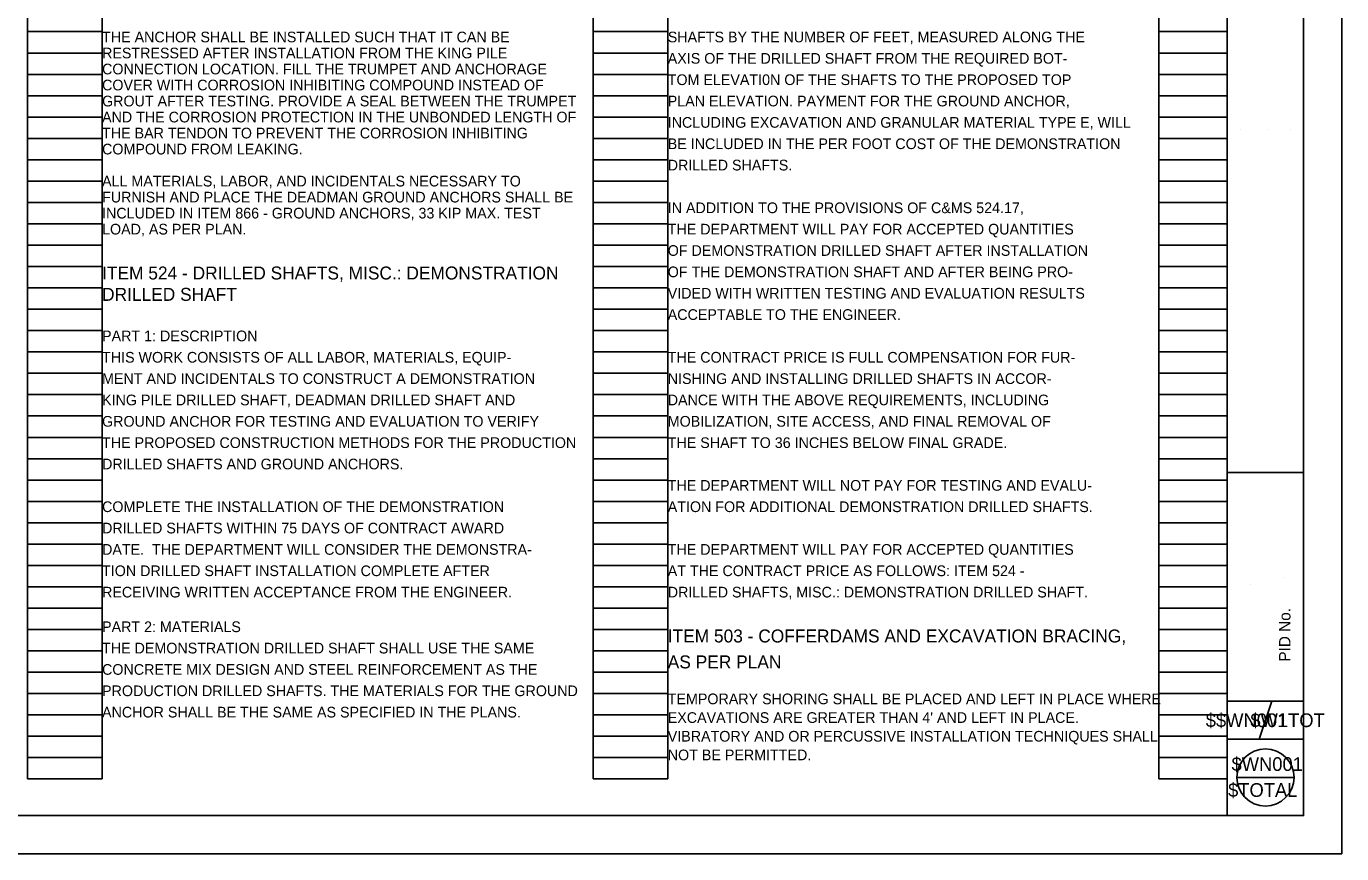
# Model space of a CAD drawing. Extents: x -0.2 to 33.8, y -0.1 to 21.9.
# Drawn here: x 16.52 to 33.78, y -0.13 to 10.72 of the extents above; entities that cross this region are included whole.
import ezdxf

# ---------------------------------------------------------------- set-up
doc = ezdxf.new("R2010")
doc.units = 0
for name, color, linetype in [('SH_Border', 7, 'Continuous'), ('SH_Cut_Line', 7, 'Continuous'), ('SH_Data', 7, 'Continuous'), ('SH_Text', 7, 'Continuous')]:
    doc.layers.add(name, color=color, linetype=linetype)

msp = doc.modelspace()

# ---------------------------------------------------------------- linework, layer by layer
at = {"layer": 'SH_Border'}
for p, q in [((32.275, 0.368), (32.275, 21.368)), ((32.275, 4.868), (33.275, 4.868)), ((32.275, 1.868), (33.275, 1.868)), ((32.692, 1.368), (32.859, 1.868)), ((32.275, 1.368), (33.275, 1.368))]:
    msp.add_line(p, q, dxfattribs=at)
msp.add_lwpolyline([(1.775, 21.368), (33.275, 21.368), (33.275, 0.368), (1.775, 0.368)], close=True, dxfattribs=at)
at = {"layer": 'SH_Cut_Line'}
msp.add_lwpolyline([(-0.225, 21.868), (33.775, 21.868), (33.775, -0.132), (-0.225, -0.132)], close=True, dxfattribs=at)
at = {"layer": 'SH_Data'}
for p, q in [((16.535, 0.848), (16.535, 21.008)), ((17.515, 0.848), (17.515, 21.008)), ((23.955, 0.848), (23.955, 21.008)), ((24.935, 0.848), (24.935, 21.008)), ((31.375, 0.848), (31.375, 21.008)), ((32.275, 0.848), (32.275, 21.008)), ((16.535, 10.648), (17.515, 10.648)), ((23.955, 10.648), (24.935, 10.648)), ((31.375, 10.648), (32.275, 10.648)), ((16.535, 10.368), (17.515, 10.368)), ((23.955, 10.368), (24.935, 10.368)), ((31.375, 10.368), (32.275, 10.368)), ((16.535, 10.088), (17.515, 10.088)), ((23.955, 10.088), (24.935, 10.088)), ((31.375, 10.088), (32.275, 10.088)), ((16.535, 9.808), (17.515, 9.808)), ((23.955, 9.808), (24.935, 9.808)), ((31.375, 9.808), (32.275, 9.808)), ((16.535, 9.528), (17.515, 9.528)), ((23.955, 9.528), (24.935, 9.528)), ((31.375, 9.528), (32.275, 9.528)), ((32.442, 9.368), (32.442, 9.368)), ((32.817, 9.368), (32.817, 9.368)), ((33.109, 9.368), (33.109, 9.368)), ((16.535, 9.248), (17.515, 9.248)), ((23.955, 9.248), (24.935, 9.248)), ((31.375, 9.248), (32.275, 9.248)), ((16.535, 8.968), (17.515, 8.968)), ((23.955, 8.968), (24.935, 8.968)), ((31.375, 8.968), (32.275, 8.968)), ((16.535, 8.688), (17.515, 8.688)), ((23.955, 8.688), (24.935, 8.688)), ((31.375, 8.688), (32.275, 8.688)), ((16.535, 8.408), (17.515, 8.408)), ((23.955, 8.408), (24.935, 8.408)), ((31.375, 8.408), (32.275, 8.408)), ((16.535, 8.128), (17.515, 8.128)), ((23.955, 8.128), (24.935, 8.128)), ((31.375, 8.128), (32.275, 8.128)), ((16.535, 7.848), (17.515, 7.848)), ((23.955, 7.848), (24.935, 7.848)), ((31.375, 7.848), (32.275, 7.848)), ((16.535, 7.568), (17.515, 7.568)), ((23.955, 7.568), (24.935, 7.568)), ((31.375, 7.568), (32.275, 7.568)), ((16.535, 7.288), (17.515, 7.288)), ((23.955, 7.288), (24.935, 7.288)), ((31.375, 7.288), (32.275, 7.288)), ((16.535, 7.008), (17.515, 7.008)), ((23.955, 7.008), (24.935, 7.008)), ((31.375, 7.008), (32.275, 7.008)), ((16.535, 6.728), (17.515, 6.728)), ((23.955, 6.728), (24.935, 6.728)), ((31.375, 6.728), (32.275, 6.728)), ((16.535, 6.448), (17.515, 6.448)), ((23.955, 6.448), (24.935, 6.448)), ((31.375, 6.448), (32.275, 6.448)), ((16.535, 6.168), (17.515, 6.168)), ((23.955, 6.168), (24.935, 6.168)), ((31.375, 6.168), (32.275, 6.168)), ((16.535, 5.888), (17.515, 5.888)), ((23.955, 5.888), (24.935, 5.888)), ((31.375, 5.888), (32.275, 5.888)), ((16.535, 5.608), (17.515, 5.608)), ((23.955, 5.608), (24.935, 5.608)), ((31.375, 5.608), (32.275, 5.608)), ((16.535, 5.328), (17.515, 5.328)), ((23.955, 5.328), (24.935, 5.328)), ((31.375, 5.328), (32.275, 5.328)), ((16.535, 5.048), (17.515, 5.048)), ((23.955, 5.048), (24.935, 5.048)), ((31.375, 5.048), (32.275, 5.048)), ((16.535, 4.768), (17.515, 4.768)), ((23.955, 4.768), (24.935, 4.768)), ((31.375, 4.768), (32.275, 4.768)), ((16.535, 4.488), (17.515, 4.488)), ((23.955, 4.488), (24.935, 4.488)), ((31.375, 4.488), (32.275, 4.488)), ((16.535, 4.208), (17.515, 4.208)), ((23.955, 4.208), (24.935, 4.208)), ((31.375, 4.208), (32.275, 4.208)), ((16.535, 3.928), (17.515, 3.928)), ((23.955, 3.928), (24.935, 3.928)), ((31.375, 3.928), (32.275, 3.928)), ((16.535, 3.648), (17.515, 3.648)), ((23.955, 3.648), (24.935, 3.648)), ((31.375, 3.648), (32.275, 3.648)), ((33.025, 3.486), (33.025, 3.486)), ((16.535, 3.368), (17.515, 3.368)), ((23.955, 3.368), (24.935, 3.368)), ((31.375, 3.368), (32.275, 3.368)), ((32.575, 3.398), (32.575, 3.398)), ((16.535, 3.088), (17.515, 3.088)), ((23.955, 3.088), (24.935, 3.088)), ((31.375, 3.088), (32.275, 3.088)), ((16.535, 2.808), (17.515, 2.808)), ((23.955, 2.808), (24.935, 2.808)), ((31.375, 2.808), (32.275, 2.808)), ((16.535, 2.528), (17.515, 2.528)), ((23.955, 2.528), (24.935, 2.528)), ((31.375, 2.528), (32.275, 2.528)), ((16.535, 2.248), (17.515, 2.248)), ((23.955, 2.248), (24.935, 2.248)), ((31.375, 2.248), (32.275, 2.248)), ((16.535, 1.968), (17.515, 1.968)), ((23.955, 1.968), (24.935, 1.968)), ((31.375, 1.968), (32.275, 1.968)), ((16.535, 1.688), (17.515, 1.688)), ((23.955, 1.688), (24.935, 1.688)), ((31.375, 1.688), (32.275, 1.688)), ((32.525, 1.618), (32.525, 1.618)), ((33.025, 1.618), (33.025, 1.618)), ((16.535, 1.408), (17.515, 1.408)), ((23.955, 1.408), (24.935, 1.408)), ((31.375, 1.408), (32.275, 1.408)), ((16.535, 1.128), (17.515, 1.128)), ((23.955, 1.128), (24.935, 1.128)), ((31.375, 1.128), (32.275, 1.128)), ((32.4, 0.868), (33.15, 0.868)), ((32.775, 0.953), (32.775, 0.953)), ((16.535, 0.848), (17.515, 0.848)), ((23.955, 0.848), (24.935, 0.848)), ((31.375, 0.848), (32.275, 0.848)), ((32.775, 0.613), (32.775, 0.613))]:
    msp.add_line(p, q, dxfattribs=at)
msp.add_circle((32.775, 0.868), 0.375, dxfattribs=at)

# ---------------------------------------------------------------- texts
for s, height, p in [('THE ANCHOR SHALL BE INSTALLED SUCH THAT IT CAN BE ', 0.14, (17.515, 10.508)), ('RESTRESSED AFTER INSTALLATION FROM THE KING PILE ', 0.14, (17.515, 10.298)), ('CONNECTION LOCATION. FILL THE TRUMPET AND ANCHORAGE ', 0.14, (17.515, 10.088)), ('COVER WITH CORROSION INHIBITING COMPOUND INSTEAD OF ', 0.14, (17.515, 9.878)), ('GROUT AFTER TESTING. PROVIDE A SEAL BETWEEN THE TRUMPET ', 0.14, (17.515, 9.668)), ('AND THE CORROSION PROTECTION IN THE UNBONDED LENGTH OF ', 0.14, (17.515, 9.458)), ('THE BAR TENDON TO PREVENT THE CORROSION INHIBITING ', 0.14, (17.515, 9.248)), ('COMPOUND FROM LEAKING.', 0.14, (17.515, 9.038)), ('ALL MATERIALS, LABOR, AND INCIDENTALS NECESSARY TO ', 0.14, (17.515, 8.618)), ('FURNISH AND PLACE THE DEADMAN GROUND ANCHORS SHALL BE ', 0.14, (17.515, 8.408)), ('INCLUDED IN ITEM 866 - GROUND ANCHORS, 33 KIP MAX. TEST ', 0.14, (17.515, 8.198)), ('LOAD, AS PER PLAN.', 0.14, (17.515, 7.988)), ('ITEM 503 - COFFERDAMS AND EXCAVATION BRACING, ', 0.17, (24.935, 2.638)), ('AS PER PLAN', 0.17, (24.935, 2.298)), ('TEMPORARY SHORING SHALL BE PLACED AND LEFT IN PLACE WHERE ', 0.14, (24.935, 1.828)), ("EXCAVATIONS ARE GREATER THAN 4' AND LEFT IN PLACE. ", 0.14, (24.935, 1.583)), ('VIBRATORY AND OR PERCUSSIVE INSTALLATION TECHNIQUES SHALL ', 0.14, (24.935, 1.338)), ('NOT BE PERMITTED.', 0.14, (24.935, 1.093))]:
    msp.add_text(s, height=height, dxfattribs=at).set_placement(p)
for s, height, rotation, p in [('PID No.', 0.15, 90, (33.103, 2.387)), ('$$WN001', 0.18, 360, (31.992, 1.528)), ('$W1TOT', 0.18, 360, (32.577, 1.528)), ('$WN001', 0.18, 360, (32.33, 0.953)), ('$TOTAL', 0.18, 360, (32.285, 0.613))]:
    msp.add_text(s, height=height, rotation=rotation, dxfattribs=at).set_placement(p)
at = {"layer": 'SH_Text'}
for s, height, p in [('SHAFTS BY THE NUMBER OF FEET, MEASURED ALONG THE', 0.14, (24.935, 10.508)), ('AXIS OF THE DRILLED SHAFT FROM THE REQUIRED BOT-', 0.14, (24.935, 10.228)), ('TOM ELEVATI0N OF THE SHAFTS TO THE PROPOSED TOP', 0.14, (24.935, 9.948)), ('PLAN ELEVATION. PAYMENT FOR THE GROUND ANCHOR, ', 0.14, (24.935, 9.668)), ('INCLUDING EXCAVATION AND GRANULAR MATERIAL TYPE E, WILL ', 0.14, (24.935, 9.388)), ('BE INCLUDED IN THE PER FOOT COST OF THE DEMONSTRATION ', 0.14, (24.935, 9.108)), ('DRILLED SHAFTS.', 0.14, (24.935, 8.828)), ('IN ADDITION TO THE PROVISIONS OF C&MS 524.17,', 0.14, (24.935, 8.268)), ('THE DEPARTMENT WILL PAY FOR ACCEPTED QUANTITIES', 0.14, (24.935, 7.988)), ('OF DEMONSTRATION DRILLED SHAFT AFTER INSTALLATION', 0.14, (24.935, 7.708)), ('ITEM 524 - DRILLED SHAFTS, MISC.: DEMONSTRATION', 0.17, (17.515, 7.398)), ('OF THE DEMONSTRATION SHAFT AND AFTER BEING PRO-', 0.14, (24.935, 7.428)), ('DRILLED SHAFT', 0.17, (17.515, 7.118)), ('VIDED WITH WRITTEN TESTING AND EVALUATION RESULTS', 0.14, (24.935, 7.148)), ('ACCEPTABLE TO THE ENGINEER.', 0.14, (24.935, 6.868)), ('PART 1: DESCRIPTION', 0.14, (17.515, 6.588)), ('THIS WORK CONSISTS OF ALL LABOR, MATERIALS, EQUIP-', 0.14, (17.515, 6.308)), ('THE CONTRACT PRICE IS FULL COMPENSATION FOR FUR-', 0.14, (24.935, 6.308)), ('MENT AND INCIDENTALS TO CONSTRUCT A DEMONSTRATION', 0.14, (17.515, 6.028)), ('NISHING AND INSTALLING DRILLED SHAFTS IN ACCOR-', 0.14, (24.935, 6.028)), ('KING PILE DRILLED SHAFT, DEADMAN DRILLED SHAFT AND', 0.14, (17.515, 5.748)), ('DANCE WITH THE ABOVE REQUIREMENTS, INCLUDING', 0.14, (24.935, 5.748)), ('GROUND ANCHOR FOR TESTING AND EVALUATION TO VERIFY', 0.14, (17.515, 5.468)), ('MOBILIZATION, SITE ACCESS, AND FINAL REMOVAL OF', 0.14, (24.935, 5.468)), ('THE PROPOSED CONSTRUCTION METHODS FOR THE PRODUCTION', 0.14, (17.515, 5.188)), ('THE SHAFT TO 36 INCHES BELOW FINAL GRADE.', 0.14, (24.935, 5.188)), ('DRILLED SHAFTS AND GROUND ANCHORS.', 0.14, (17.515, 4.908)), ('THE DEPARTMENT WILL NOT PAY FOR TESTING AND EVALU-', 0.14, (24.935, 4.628)), ('COMPLETE THE INSTALLATION OF THE DEMONSTRATION', 0.14, (17.515, 4.348)), ('ATION FOR ADDITIONAL DEMONSTRATION DRILLED SHAFTS.', 0.14, (24.935, 4.348)), ('DRILLED SHAFTS WITHIN 75 DAYS OF CONTRACT AWARD', 0.14, (17.515, 4.068)), ('DATE.  THE DEPARTMENT WILL CONSIDER THE DEMONSTRA-', 0.14, (17.515, 3.788)), ('THE DEPARTMENT WILL PAY FOR ACCEPTED QUANTITIES', 0.14, (24.935, 3.788)), ('TION DRILLED SHAFT INSTALLATION COMPLETE AFTER', 0.14, (17.515, 3.508)), ('AT THE CONTRACT PRICE AS FOLLOWS: ITEM 524 -', 0.14, (24.935, 3.508)), ('RECEIVING WRITTEN ACCEPTANCE FROM THE ENGINEER.', 0.14, (17.515, 3.228)), ('DRILLED SHAFTS, MISC.: DEMONSTRATION DRILLED SHAFT.', 0.14, (24.935, 3.228)), ('PART 2: MATERIALS', 0.14, (17.515, 2.774)), ('THE DEMONSTRATION DRILLED SHAFT SHALL USE THE SAME', 0.14, (17.515, 2.494)), ('CONCRETE MIX DESIGN AND STEEL REINFORCEMENT AS THE', 0.14, (17.515, 2.214)), ('PRODUCTION DRILLED SHAFTS. THE MATERIALS FOR THE GROUND', 0.14, (17.515, 1.934)), ('ANCHOR SHALL BE THE SAME AS SPECIFIED IN THE PLANS.', 0.14, (17.515, 1.654))]:
    msp.add_text(s, height=height, dxfattribs=at).set_placement(p)

doc.saveas('drawing.dxf')
